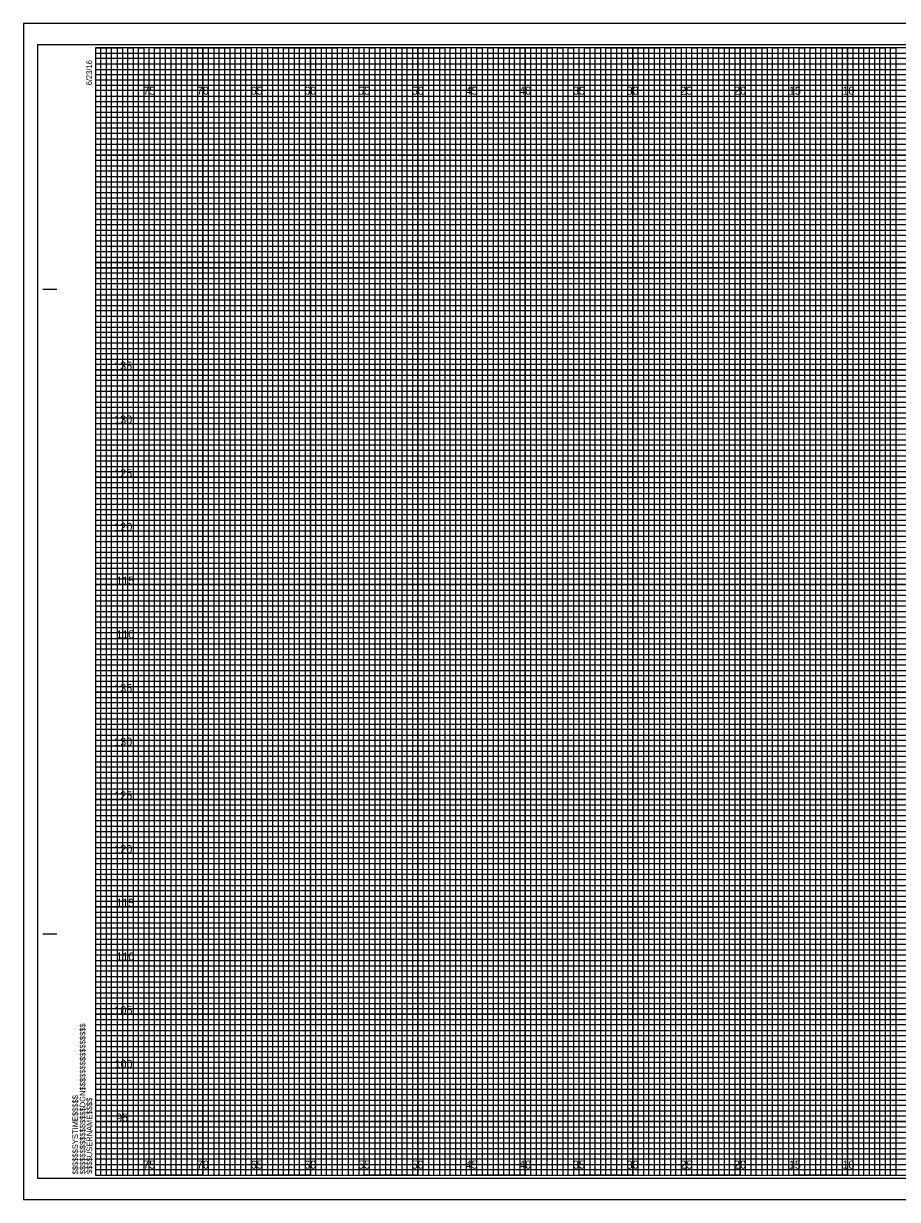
# Model space of a CAD drawing. Extents: x -7 to 182, y -2 to 1647.
# Drawn here: x -6.7 to 74.6, y 877.8 to 987.2 of the extents above; entities that cross this region are included whole.
import ezdxf

# ---------------------------------------------------------------- set-up
doc = ezdxf.new("R2010")
doc.units = 0
for name, color, linetype in [('Exist Cross Section Cell', 7, 'Continuous'), ('Exist XS Ground Line', 7, 'Continuous'), ('Prop CMT Pvmt Course 3', 7, 'Continuous'), ('Prop CMT Pvmt Wedge Surface 1', 7, 'Continuous'), ('Prop CMT Pvmt Wedge Surface 2', 7, 'Continuous'), ('Prop CMT Pvmt Wedge Surface 3', 7, 'Continuous'), ('Prop CMT Shld Paved Course 1', 7, 'Continuous'), ('Prop CMT Shld Paved Course 2', 7, 'Continuous'), ('Prop CMT Shld Paved Course 3', 7, 'Continuous'), ('Prop CMT Slope Grass', 7, 'Continuous'), ('Prop CMT Subgrade Earthwork', 7, 'Continuous')]:
    doc.layers.add(name, color=color, linetype=linetype)

msp = doc.modelspace()

# ---------------------------------------------------------------- linework, layer by layer
at = {"layer": 'Exist XS Ground Line'}
for p, q in [((5, 985), (0, 985)), ((5, 880), (5, 985)), ((15, 985), (10, 985)), ((10, 985), (10, 880)), ((15, 880), (15, 985)), ((25, 985), (20, 985)), ((20, 985), (20, 880)), ((25, 880), (25, 985)), ((35, 985), (30, 985)), ((30, 985), (30, 880)), ((35, 880), (35, 985)), ((45, 985), (40, 985)), ((40, 985), (40, 880)), ((45, 880), (45, 985)), ((55, 985), (50, 985)), ((50, 985), (50, 880)), ((55, 880), (55, 985)), ((65, 985), (60, 985)), ((60, 985), (60, 880)), ((65, 880), (65, 985)), ((75, 985), (70, 985)), ((70, 985), (70, 880)), ((10, 880), (5, 880)), ((20, 880), (15, 880)), ((30, 880), (25, 880)), ((40, 880), (35, 880)), ((50, 880), (45, 880)), ((60, 880), (55, 880)), ((70, 880), (65, 880))]:
    msp.add_line(p, q, dxfattribs=at)
for points in [[(0, 980), (160, 980), (160, 975), (0, 975)], [(0, 970), (160, 970), (160, 965), (0, 965)], [(0, 960), (160, 960), (160, 955), (0, 955)], [(0, 950), (160, 950), (160, 945), (0, 945)], [(0, 940), (160, 940), (160, 935), (0, 935)], [(0, 930), (160, 930), (160, 925), (0, 925)], [(0, 920), (160, 920), (160, 915), (0, 915)], [(0, 910), (160, 910), (160, 905), (0, 905)], [(0, 900), (160, 900), (160, 895), (0, 895)], [(0, 890), (160, 890), (160, 885), (0, 885)]]:
    msp.add_lwpolyline(points, dxfattribs=at)
at = {"layer": 'Prop CMT Pvmt Course 3'}
msp.add_lwpolyline([(-6.7, 877.75), (161.65, 877.75), (161.65, 987.25), (-6.7, 987.25)], close=True, dxfattribs=at)
at = {"layer": 'Prop CMT Pvmt Wedge Surface 1'}
for p, q in [((0, 984.5), (130, 984.5)), ((130, 983.99), (0, 983.99)), ((0, 983.99), (0, 983.5)), ((0, 983.5), (130, 983.5)), ((130, 982.95), (0, 982.95)), ((0, 982.95), (0, 982)), ((0, 982), (160, 982))]:
    msp.add_line(p, q, dxfattribs=at)
for points in [[(0, 981.5), (135, 981.5), (160, 981.5), (160, 981), (0, 981)], [(0, 980.5), (160, 980.5), (160, 979.5), (0, 979.5)], [(0, 979), (160, 979), (160, 978.5), (0, 978.49)], [(0, 978), (160, 978), (160, 977), (0, 977)], [(0, 976.5), (160, 976.5), (160, 976), (0, 976)], [(0, 975.5), (160, 975.5), (160, 974.5), (0, 974.5)], [(0, 974), (160, 974), (160, 973.5), (0, 973.5)], [(0, 973), (160, 973), (160, 972), (0, 972)], [(0, 971.5), (160, 971.5), (160, 971), (0, 971)], [(0, 970.5), (160, 970.5), (160, 969.5), (0, 969.5)], [(0, 969), (160, 969), (160, 968.5), (0, 968.5)], [(0, 968), (160, 968), (160, 966.98), (160, 966.5), (160, 966), (0, 966)], [(0, 967), (160, 967), (160, 966.5), (0, 966.5)], [(0, 965.5), (160, 965.5), (160, 964.5), (0, 964.51)], [(0, 964.51), (160, 964.5), (160, 964), (0, 964)], [(0, 963.5), (160, 963.5), (160, 963), (0, 963)], [(0, 962), (160, 962), (160, 961.5), (0, 961.5)], [(0, 961), (160, 961), (160, 960.5), (0, 960.5)], [(-0.04, 959.45), (160, 959.45), (160, 958.94), (-0.04, 958.94)], [(0, 958.5), (160, 958.5), (160, 958), (0, 958)], [(0, 957), (160, 957), (160, 956.5), (0, 956.5)], [(0, 956), (160, 956), (160, 955.5), (0, 955.5)], [(0, 954.5), (160, 954.5), (160, 954), (0, 954)], [(0, 953.5), (160, 953.5), (160, 953), (0, 953)], [(0, 952), (160, 952), (160, 951.5), (0, 951.5)], [(0, 951), (160, 951), (160, 950.5), (0, 950.5)], [(0, 949.5), (160, 949.5), (160, 948.99), (0, 949)], [(0, 948.5), (160, 948.5), (160, 948), (0, 948)], [(0, 947), (160, 947), (160, 946.5), (0, 946.5)], [(0, 946), (160, 946), (160, 945.5), (0, 945.5)], [(0, 944.5), (160, 944.5), (160, 944), (0, 944)], [(0, 943.5), (160, 943.5), (160, 943), (0, 943)], [(0, 942), (160, 942), (160, 941.5), (0, 941.5)], [(0, 941), (160, 941), (160, 940.5), (0, 940.5)], [(0, 939.5), (160, 939.5), (160, 939), (0, 939)], [(0, 938.5), (160.03, 938.46), (160, 938), (0, 938)], [(0, 937), (160, 937), (160, 936.5), (0, 936.5)], [(0, 936), (160, 936), (160, 935.5), (0, 935.5)], [(0, 934.5), (160, 934.5), (160, 934), (0, 934)], [(0, 933.5), (160, 933.5), (160, 933), (0, 933)], [(0, 932), (160, 932), (160, 931.5), (0, 931.5)], [(0, 931), (160, 931), (160, 930.5), (0, 930.5)], [(0, 929.5), (160, 929.5), (160, 929), (0, 929)], [(0, 928.5), (160, 928.5), (160, 928), (0, 928)], [(0, 927), (160, 927), (160, 926.5), (0, 926.5)], [(0, 926), (160, 926), (160, 925.5), (0, 925.5)], [(0, 924.5), (160, 924.5), (160, 924), (0, 924)], [(0, 923.5), (160, 923.5), (160, 923), (0, 923)], [(0, 922), (160, 922), (160, 921.5), (0, 921.5)], [(0, 921), (160, 921), (160, 920.5), (0, 920.5)], [(0, 919.5), (160, 919.5), (160, 918.99), (0, 919)], [(0, 918.5), (160, 918.5), (160, 918), (0, 918)], [(0, 917), (160, 917), (160, 916.5), (0, 916.5)], [(0, 916), (160, 916), (160, 915.5), (0, 915.5)], [(0, 914.5), (160, 914.5), (160, 914), (0, 914)], [(0, 913.5), (160, 913.5), (160, 913), (0, 913)], [(0, 912), (160, 912), (160, 911.5), (0, 911.5)], [(0, 911), (160, 911), (160, 910.5), (0, 910.5)], [(0, 909.5), (160, 909.5), (160, 909), (0, 909)], [(0, 908.5), (160.03, 908.46), (160, 908), (0, 908)], [(0, 907), (160, 907), (160, 906.5), (0, 906.5)], [(0, 906), (160, 906), (160, 905.5), (0, 905.5)], [(0, 904.5), (160, 904.5), (160, 904), (0, 904)], [(0, 903.5), (160, 903.5), (160, 903), (0, 903)], [(0, 902), (160, 902), (160, 901.5), (0, 901.5)], [(0, 901), (160, 901), (160, 900.5), (0, 900.5)], [(0, 899.5), (160, 899.5), (160, 899), (0, 899)], [(0, 898.5), (160, 898.5), (160, 898), (0, 898)], [(0, 897), (160, 897), (160, 896.5), (0, 896.5)], [(0, 896), (160, 896), (160, 895.5), (0, 895.5)], [(0, 894.5), (160, 894.5), (160, 894), (0, 894)], [(0, 893.5), (160, 893.5), (160, 893), (0, 893)], [(0, 892), (160, 892), (160, 891.5), (0, 891.5)], [(0, 891), (160, 891), (160, 890.5), (0, 890.5)], [(0, 889.5), (160, 889.5), (160, 889), (0, 889)], [(0, 888.5), (160, 888.5), (160, 888), (0, 888)], [(0, 887), (160, 887), (160, 886.5), (0, 886.5)], [(0, 886), (160, 886), (160, 885.5), (0, 885.5)], [(0, 884.5), (160, 884.5), (160, 884), (0, 884)], [(0, 883.5), (160, 883.5), (160, 883), (0, 883)], [(0, 882), (160, 882), (160, 881.5), (0, 881.5)], [(0, 881), (160, 881), (160, 880.5), (0, 880.5)]]:
    msp.add_lwpolyline(points, dxfattribs=at)
at = {"layer": 'Prop CMT Pvmt Wedge Surface 2'}
for p, q in [((-4.9, 962.5), (-3.65, 962.5)), ((-4.85, 962.5), (-3.6, 962.5)), ((-4.9, 902.5), (-3.65, 902.5)), ((-4.85, 902.5), (-3.6, 902.5)), ((0, 880), (0, 880)), ((0, 880), (0, 880)), ((0, 880), (0, 880)), ((0, 880), (0, 880)), ((0, 880), (0, 880)), ((0, 880), (0, 880)), ((0, 880), (0, 880))]:
    msp.add_line(p, q, dxfattribs=at)
msp.add_lwpolyline([(160, 985), (0, 985), (0, 880), (160, 880)], close=True, dxfattribs=at)
at = {"layer": 'Prop CMT Pvmt Wedge Surface 3'}
for points in [[(0, 880), (0.5, 880), (0.5, 985), (1, 985), (1, 880)], [(1, 880), (1.5, 880), (1.5, 985), (2, 985), (2, 880)], [(2.5, 880), (3, 880), (3, 985), (3.5, 985), (3.5, 880)], [(3.5, 880), (4, 880), (4, 985), (4.5, 985), (4.5, 880)], [(5, 880), (5.5, 880), (5.5, 985), (6, 985), (6, 880)], [(6, 880), (6.5, 880), (6.5, 985), (7, 985), (7, 880)], [(7.5, 880), (8, 880), (8, 985), (8.5, 985), (8.5, 880)], [(8.5, 880), (9, 880), (9, 985), (9.5, 985), (9.5, 880)], [(10, 880), (10.5, 880), (10.5, 985), (11, 985), (11, 880)], [(11, 880), (11.5, 880), (11.5, 985), (12, 985), (12, 880)], [(12.5, 880), (13, 880), (13, 985), (13.5, 985), (13.5, 880)], [(13.5, 880), (14, 880), (14, 985), (14.5, 985), (14.5, 880)], [(15, 880), (15.5, 880), (15.5, 985), (16, 985), (16, 880)], [(16, 880), (16.5, 880), (16.5, 985), (17, 985), (17, 880)], [(17.5, 880), (18, 880), (18, 985), (18.5, 985), (18.5, 880)], [(18.5, 880), (19, 880), (19, 985), (19.5, 985), (19.5, 880)], [(20, 880), (20.5, 880), (20.5, 985), (21, 985), (21, 880)], [(21, 880), (21.5, 880), (21.5, 985), (22, 985), (22, 880)], [(22.5, 880), (23, 880), (23, 985), (23.5, 985), (23.5, 880)], [(23.5, 880), (24, 880), (24, 985), (24.5, 985), (24.5, 880)], [(25, 880), (25.5, 880), (25.5, 985), (26, 985), (26, 880)], [(26, 880), (26.5, 880), (26.5, 985), (27, 985), (27, 880)], [(27.5, 880), (28, 880), (28, 985), (28.5, 985), (28.5, 880)], [(28.5, 880), (29, 880), (29, 985), (29.5, 985), (29.5, 880)], [(30, 880), (30.5, 880), (30.5, 985), (31, 985), (31, 880)], [(31, 880), (31.5, 880), (31.5, 985), (32, 985), (32, 880)], [(32.5, 880), (33, 880), (33, 985), (33.5, 985), (33.5, 880)], [(33.5, 880), (34, 880), (34, 985), (34.5, 985), (34.5, 880)], [(35, 880), (35.5, 880), (35.5, 985), (36, 985), (36, 880)], [(36, 880), (36.5, 880), (36.5, 985), (37, 985), (37, 880)], [(37.5, 880), (38, 880), (38, 985), (38.5, 985), (38.5, 880)], [(38.5, 880), (39, 880), (39, 985), (39.5, 985), (39.5, 880)], [(40, 880), (40.5, 880), (40.5, 985), (41, 985), (41, 880)], [(41, 880), (41.5, 880), (41.5, 985), (42, 985), (42, 880)], [(42.5, 880), (43, 880), (43, 985), (43.5, 985), (43.5, 880)], [(43.5, 880), (44, 880), (44, 985), (44.5, 985), (44.5, 880)], [(45, 880), (45.5, 880), (45.5, 985), (46, 985), (46, 880)], [(46, 880), (46.5, 880), (46.5, 985), (47, 985), (47, 880)], [(47.5, 880), (48, 880), (48, 985), (48.5, 985), (48.5, 880)], [(48.5, 880), (49, 880), (49, 985), (49.5, 985), (49.5, 880)], [(50, 880), (50.5, 880), (50.5, 985), (51, 985), (51, 880)], [(51, 880), (51.5, 880), (51.5, 985), (52, 985), (52, 880)], [(52.5, 880), (53, 880), (53, 985), (53.5, 985), (53.5, 880)], [(53.5, 880), (54, 880), (54, 985), (54.5, 985), (54.5, 880)], [(55, 880), (55.5, 880), (55.5, 985), (56, 985), (56, 880)], [(56, 880), (56.5, 880), (56.5, 985), (57, 985), (57, 880)], [(57.5, 880), (58, 880), (58, 985), (58.5, 985), (58.5, 880)], [(58.5, 880), (59, 880), (59, 985), (59.5, 985), (59.5, 880)], [(60, 880), (60.5, 880), (60.5, 985), (61, 985), (61, 880)], [(61, 880), (61.5, 880), (61.5, 985), (62, 985), (62, 880)], [(62.5, 880), (63, 880), (63, 985), (63.5, 985), (63.5, 880)], [(63.5, 880), (64, 880), (64, 985), (64.5, 985), (64.5, 880)], [(65, 880), (65.5, 880), (65.5, 985), (66, 985), (66, 880)], [(66, 880), (66.5, 880), (66.5, 985), (67, 985), (67, 880)], [(67.5, 880), (68, 880), (68, 985), (68.5, 985), (68.5, 880)], [(68.5, 880), (69, 880), (69, 985), (69.5, 985), (69.5, 880)], [(70, 880), (70.5, 880), (70.5, 985), (71, 985), (71, 880)], [(71, 880), (71.5, 880), (71.5, 985), (72, 985), (72, 880)], [(72.5, 880), (73, 880), (73, 985), (73.5, 985), (73.5, 880)], [(73.5, 880), (74, 880), (74, 985), (74.5, 985), (74.5, 880)]]:
    msp.add_lwpolyline(points, dxfattribs=at)
at = {"layer": 'Prop CMT Shld Paved Course 1'}
for p, q in [((5, 880), (5, 985)), ((10, 880), (10, 985)), ((15, 880), (15, 985)), ((20, 880), (20, 985)), ((25, 880), (25, 985)), ((30, 880), (30, 985)), ((35, 880), (35, 985)), ((40, 880), (40, 985)), ((45, 880), (45, 985)), ((50, 880), (50, 985)), ((55, 880), (55, 985)), ((60, 880), (60, 985)), ((65, 880), (65, 985)), ((70, 880), (70, 985)), ((0, 980), (160, 980)), ((0, 975), (160, 975)), ((0, 970), (160, 970)), ((0, 965), (160, 965)), ((0, 960), (160, 960)), ((0, 955), (160, 955)), ((0, 950), (160, 950)), ((0, 945), (160, 945)), ((0, 940), (160, 940)), ((0, 935), (160, 935)), ((0, 930), (160, 930)), ((0, 925), (160, 925)), ((0, 920), (160, 920)), ((0, 915), (160, 915)), ((0, 910), (160, 910)), ((0, 905), (160, 905)), ((0, 900), (160, 900)), ((0, 895), (160, 895)), ((0, 890), (160, 890)), ((0, 885), (160, 885))]:
    msp.add_line(p, q, dxfattribs=at)
at = {"layer": 'Prop CMT Shld Paved Course 2'}
for p, q in [((161.65, 987.25), (-6.7, 987.25)), ((-6.7, 987.25), (-6.7, 877.75)), ((-6.7, 877.75), (161.65, 877.75))]:
    msp.add_line(p, q, dxfattribs=at)
at = {"layer": 'Prop CMT Slope Grass'}
msp.add_lwpolyline([(-5.4, 879.75), (161.2, 879.75), (161.2, 985.25), (-5.4, 985.25)], close=True, dxfattribs=at)
at = {"layer": 'Prop CMT Subgrade Earthwork'}
for points in [[(0, 985), (2.5, 985), (2.5, 880), (7.5, 880), (7.5, 985), (12.5, 985), (12.5, 880), (17.5, 880), (17.5, 985), (22.5, 985), (22.5, 880), (27.5, 880), (27.5, 985), (32.5, 985), (32.5, 880), (37.5, 880), (37.5, 985), (42.5, 985), (42.5, 880), (47.5, 880), (47.5, 985), (52.5, 985), (52.5, 880), (57.5, 880), (57.5, 985), (62.5, 985), (62.5, 880), (67.5, 880), (67.5, 985), (72.5, 985), (72.5, 880), (77.5, 880)], [(0, 982.5), (137.5, 982.5)], [(0, 972.5), (160, 972.5), (160, 977.5), (0, 977.5)], [(0, 962.5), (160, 962.5), (160, 967.5), (0, 967.5)], [(0, 952.5), (160, 952.5), (160, 957.5), (0, 957.5)], [(0, 942.5), (160, 942.5), (160, 947.5), (0, 947.5)], [(0, 932.5), (160, 932.5), (160, 937.5), (0, 937.5)], [(0, 922.5), (160, 922.5), (160, 927.5), (0, 927.5)], [(0, 912.5), (160, 912.5), (160, 917.5), (0, 917.5)], [(0, 902.5), (160, 902.5), (160, 907.5), (0, 907.5)], [(0, 892.5), (160, 892.5), (160, 897.5), (0, 897.5)], [(0, 882.5), (160, 882.5), (160, 887.5), (0, 887.5)]]:
    msp.add_lwpolyline(points, dxfattribs=at)

# ---------------------------------------------------------------- texts
at = {"layer": 'Exist Cross Section Cell'}
for s, p in [('75', (4.44, 980.62)), ('70', (9.43, 980.62)), ('65', (14.44, 980.62)), ('60', (19.43, 980.62)), ('55', (24.44, 980.62)), ('50', (29.43, 980.62)), ('45', (34.44, 980.62)), ('40', (39.43, 980.62)), ('35', (44.44, 980.62)), ('30', (49.43, 980.62)), ('25', (54.44, 980.62)), ('20', (59.43, 980.62)), ('15', (64.53, 980.62)), ('10', (69.52, 980.62)), ('75', (4.44, 880.62)), ('70', (9.43, 880.62)), ('65', (14.44, 880.62)), ('60', (19.43, 880.62)), ('55', (24.44, 880.62)), ('50', (29.43, 880.62)), ('45', (34.44, 880.62)), ('40', (39.43, 880.62)), ('35', (44.44, 880.62)), ('30', (49.43, 880.62)), ('25', (54.44, 880.62)), ('20', (59.43, 880.62)), ('15', (64.53, 880.62)), ('10', (69.52, 880.62))]:
    msp.add_text(s, height=0.75, dxfattribs=at).set_placement(p)
at = {"layer": 'Prop CMT Pvmt Wedge Surface 2'}
for s, p in [('6/23/16', (-0.33, 981.5)), ('$$$$$$$$$$$$$$$$DGN$$$$$$$$$$$$$$$$', (-0.94, 880.09)), ('$$$$$$SYSTIME$$$$$', (-1.63, 880.09)), ('$$$$USERNAME$$$$', (-0.31, 880.12))]:
    msp.add_text(s, height=0.525, rotation=90, dxfattribs=at).set_placement(p)
at = {"layer": 'Prop CMT Shld Paved Course 3'}
for s, p in [('135', (1.74, 955)), ('130', (1.74, 950)), ('125', (1.74, 945)), ('120', (1.75, 940)), ('115', (1.93, 935)), ('110', (1.94, 930)), ('135', (1.74, 925)), ('130', (1.74, 920)), ('125', (1.74, 915)), ('120', (1.75, 910)), ('115', (1.93, 905)), ('110', (1.94, 900)), ('105', (1.76, 895)), ('100', (1.77, 890)), ('95', (1.92, 885))]:
    msp.add_text(s, height=0.75, dxfattribs=at).set_placement(p)

doc.saveas('drawing.dxf')
